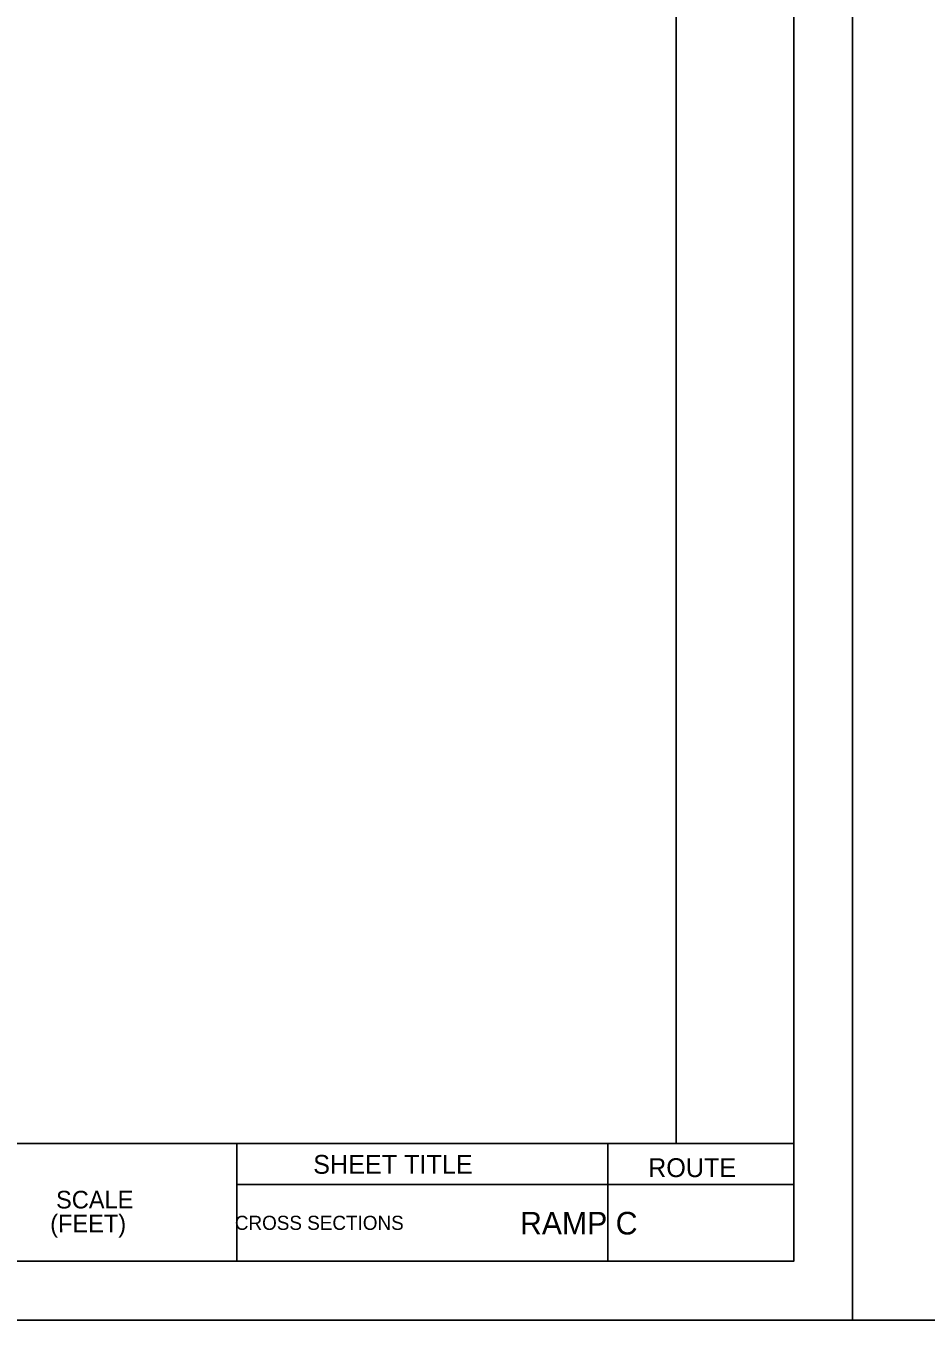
# Model space of a CAD drawing. Extents: x 1802116 to 1804496, y 250064 to 250284.
# Drawn here: x 1803065.7 to 1803142.3, y 250064.4 to 250174.4 of the extents above; entities that cross this region are included whole.
import ezdxf

# ---------------------------------------------------------------- set-up
doc = ezdxf.new("R2010")
doc.units = 0
for name, color, linetype in [('ANNO-SHT', 7, 'Continuous'), ('ANNO-SYMB', 7, 'Continuous'), ('ANNO-TXT', 7, 'Continuous'), ('Level 6', 7, 'Continuous'), ('Level 62', 7, 'Continuous'), ('SHT-BDR', 7, 'Continuous'), ('SHT-BNDRY', 7, 'Continuous')]:
    doc.layers.add(name, color=color, linetype=linetype)

msp = doc.modelspace()

# ---------------------------------------------------------------- linework, layer by layer
at = {"layer": 'ANNO-TXT'}
for p, q in [((1803083.66, 250075.96), (1803115.19, 250075.96)), ((1803115.19, 250075.96), (1803131, 250075.96))]:
    msp.add_line(p, q, dxfattribs=at)
at = {"layer": 'Level 6'}
msp.add_line((1803131, 250079.43), (1803083.66, 250079.43), dxfattribs=at)
at = {"layer": 'Level 62'}
for points in [[(1802796, 250064.42), (1803136, 250064.42), (1803136, 250284.42), (1802796, 250284.42)], [(1803136, 250064.42), (1803476, 250064.42), (1803476, 250284.42), (1803136, 250284.42)]]:
    msp.add_lwpolyline(points, close=True, dxfattribs=at)
at = {"layer": 'SHT-BDR'}
msp.add_lwpolyline([(1802821, 250079.43), (1803121, 250079.43), (1803121, 250269.43), (1802821, 250269.43)], close=True, dxfattribs=at)
at = {"layer": 'SHT-BNDRY'}
for p, q in [((1803083.66, 250069.42), (1803083.66, 250079.43)), ((1803115.19, 250069.42), (1803115.19, 250079.43))]:
    msp.add_line(p, q, dxfattribs=at)
msp.add_lwpolyline([(1802808.5, 250069.42), (1803131, 250069.42), (1803131, 250279.42), (1802808.5, 250279.42)], close=True, dxfattribs=at)

# ---------------------------------------------------------------- texts
at = {"layer": 'ANNO-SHT'}
for s, height, p in [('          CROSS SECTIONS          ', 1.2, (1803079.03, 250072.09)), ('       RAMP C       ', 1.92, (1803102.74, 250071.7))]:
    msp.add_text(s, height=height, rotation=360, dxfattribs=at).set_placement(p)
at = {"layer": 'ANNO-SYMB'}
for s, p in [('SCALE', (1803068.29, 250073.91)), ('(FEET)', (1803067.79, 250071.88))]:
    msp.add_text(s, height=1.499, rotation=0.0572, dxfattribs=at).set_placement(p)
at = {"layer": 'ANNO-TXT'}
for s, p in [('SHEET TITLE', (1803090.15, 250076.86)), ('ROUTE', (1803118.62, 250076.58))]:
    msp.add_text(s, height=1.6, dxfattribs=at).set_placement(p)

doc.saveas('drawing.dxf')
